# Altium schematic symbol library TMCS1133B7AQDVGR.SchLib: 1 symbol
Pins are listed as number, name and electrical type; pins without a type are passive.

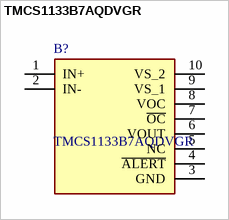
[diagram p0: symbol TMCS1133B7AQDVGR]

## TMCS1133B7AQDVGR
designator B?
Board Mount Current Sensors +/-1300V reinforced isolation 80ARMS 1M; Manufacturer_Name: Texas Instruments; Geometry.Height: 2.65mm
footprint TMCS1133B7AQDVGR
pins: 1 IN+, 2 IN-, 3 GND, 4 ~{ALERT}, 5 NC, 6 VOUT, 7 ~{OC}, 8 VOC, 9 VS_1, 10 VS_2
